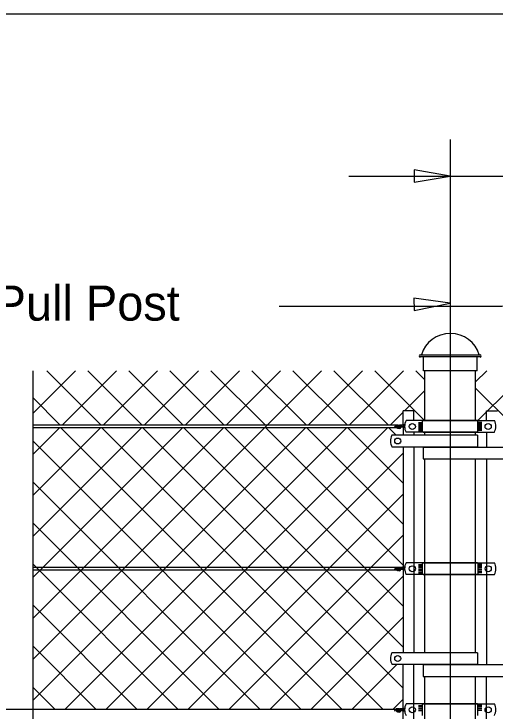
# Model space of a CAD drawing. Extents: x 0 to 41.1, y 0 to 26.4.
# Drawn here: x 23.735 to 26.501, y 22.394 to 26.4 of the extents above; entities that cross this region are included whole.
import ezdxf

# ---------------------------------------------------------------- set-up
doc = ezdxf.new("R2010")
doc.units = 0
for name, color, linetype in [('CL_Major', 7, 'Continuous'), ('Dimension', 7, 'Continuous'), ('Miscellaneous', 7, 'Continuous'), ('Miscellaneous1', 7, 'Continuous'), ('SteelMisc', 7, 'Continuous'), ('TextStructures', 7, 'Continuous')]:
    doc.layers.add(name, color=color, linetype=linetype)

msp = doc.modelspace()

# ---------------------------------------------------------------- linework, layer by layer
at = {"layer": 'CL_Major'}
msp.add_line((26.2429, 25.6784), (26.2429, 12.3953), dxfattribs=at)
at = {"layer": 'Dimension'}
msp.add_line((25.6609, 25.4682), (35.6727, 25.4682), dxfattribs=at)
for points in [[(26.2429, 25.4682), (26.0347, 25.5034), (26.0347, 25.4329)], [(26.2429, 24.737), (26.0337, 24.766), (26.0358, 24.6954)]]:
    msp.add_lwpolyline(points, close=True, dxfattribs=at)
msp.add_lwpolyline([(23.8431, 24.349), (23.8431, 21.1819), (23.9465, 21.1819), (23.8431, 21.1369), (23.7398, 21.0919), (23.8431, 21.0919), (23.8431, 20.1983)], dxfattribs=at)
msp.add_open_spline([(25.2588, 24.7214), (25.7125, 24.7214), (27.3088, 24.7214), (28.5763, 24.9737)], degree=2, dxfattribs=at)
at = {"layer": 'Miscellaneous'}
for p, q in [((24.0882, 24.349), (23.8431, 24.104)), ((24.2372, 24.0365), (23.9247, 24.349)), ((24.3239, 24.349), (24.0113, 24.0365)), ((24.4729, 24.0365), (24.1604, 24.349)), ((24.5596, 24.349), (24.247, 24.0365)), ((24.7086, 24.0365), (24.3961, 24.349)), ((24.7953, 24.349), (24.4827, 24.0365)), ((24.9443, 24.0365), (24.6318, 24.349)), ((25.031, 24.349), (24.7184, 24.0365)), ((25.18, 24.0365), (24.8675, 24.349)), ((25.2667, 24.349), (24.9541, 24.0365)), ((25.4157, 24.0365), (25.1032, 24.349)), ((25.5024, 24.349), (25.1898, 24.0365)), ((25.6514, 24.0365), (25.3389, 24.349)), ((25.7381, 24.349), (25.4255, 24.0365)), ((25.8871, 24.0365), (25.5746, 24.349)), ((25.9738, 24.349), (25.6612, 24.0365)), ((26.0957, 24.0637), (25.8103, 24.349)), ((26.0971, 24.298), (26.046, 24.349)), ((26.3887, 24.2852), (26.4526, 24.349)), ((26.4023, 24.0631), (26.6883, 24.349)), ((25.4108, 24.2575), (23.8431, 22.6898)), ((26.0971, 24.2366), (25.9803, 24.1198)), ((26.3887, 24.2494), (26.6017, 24.0365)), ((24.0015, 24.0365), (23.8431, 24.1949)), ((25.972, 24.1116), (25.8969, 24.0365)), ((25.4108, 24.0218), (23.8431, 22.4541)), ((24.9394, 24.0218), (23.8431, 22.9255)), ((24.7037, 24.0218), (23.8431, 23.1612)), ((24.468, 24.0218), (23.8431, 23.3969)), ((24.2323, 24.0218), (23.8431, 23.6326)), ((23.9966, 24.0218), (23.8431, 23.8683)), ((25.6205, 22.4048), (24.0035, 24.0218)), ((25.6465, 24.0218), (24.0295, 22.4048)), ((25.8562, 22.4048), (24.2392, 24.0218)), ((25.8822, 24.0218), (24.2652, 22.4048)), ((25.972, 22.5246), (24.4749, 24.0218)), ((25.972, 22.7603), (24.7106, 24.0218)), ((25.972, 22.996), (24.9463, 24.0218)), ((25.972, 23.2317), (25.182, 24.0218)), ((25.972, 23.4674), (25.4177, 24.0218)), ((25.972, 23.7031), (25.6534, 24.0218)), ((25.9323, 23.9786), (25.8891, 24.0218)), ((25.3848, 22.4048), (23.8431, 23.9464)), ((25.972, 23.8759), (24.5009, 22.4048)), ((25.1491, 22.4048), (23.8431, 23.7107)), ((25.972, 23.6402), (24.7366, 22.4048)), ((24.9134, 22.4048), (23.8431, 23.475)), ((25.972, 23.4045), (24.9723, 22.4048)), ((24.6777, 22.4048), (23.8431, 23.2393)), ((25.972, 23.1688), (25.208, 22.4048)), ((24.442, 22.4048), (23.8431, 23.0036)), ((25.972, 22.9331), (25.4437, 22.4048)), ((24.2063, 22.4048), (23.8447, 22.7664)), ((25.9356, 22.6609), (25.6794, 22.4048)), ((23.9706, 22.4048), (23.8431, 22.5322)), ((25.972, 22.4617), (25.9151, 22.4048))]:
    msp.add_line(p, q, dxfattribs=at)
at = {"layer": 'Miscellaneous1'}
msp.add_lwpolyline([(0, 26.4), (41.0667, 26.4), (41.0667, 0), (0, 0)], close=True, dxfattribs=at)
at = {"layer": 'SteelMisc'}
for p, q in [((26.0706, 24.441), (26.4152, 24.441)), ((26.4152, 24.4288), (26.0706, 24.4288)), ((26.0889, 24.349), (26.0889, 24.4288)), ((26.397, 24.349), (26.397, 24.4288)), ((26.397, 24.349), (26.0889, 24.349)), ((26.0971, 24.0636), (26.0971, 24.349)), ((26.3887, 24.0636), (26.3887, 24.349)), ((25.972, 24.0396), (25.972, 24.1198)), ((26.0345, 24.1198), (25.972, 24.1198)), ((26.0345, 24.0636), (26.0345, 24.1198)), ((26.4512, 24.0636), (26.4512, 24.1198)), ((26.4512, 24.1198), (26.5137, 24.1198)), ((25.9336, 24.0365), (23.8431, 24.0365)), ((25.9817, 24.0412), (25.9524, 24.0366)), ((25.972, 24.0366), (25.972, 23.9786)), ((26.3988, 24.0637), (25.989, 24.0637)), ((26.0604, 24.0528), (26.0833, 24.0528)), ((26.0604, 24.0473), (26.0833, 24.0473)), ((26.0604, 24.0393), (26.0833, 24.0393)), ((26.0833, 23.9959), (26.0833, 24.0637)), ((26.0872, 24.0637), (26.4969, 24.0637)), ((26.4254, 24.0528), (26.4024, 24.0528)), ((26.4254, 24.0473), (26.4024, 24.0473)), ((26.4254, 24.0393), (26.4024, 24.0393)), ((26.4025, 23.9959), (26.4025, 24.0637)), ((25.9349, 24.0218), (23.8431, 24.0218)), ((25.981, 24.0207), (25.9474, 24.0264)), ((25.9806, 24.0255), (25.9508, 24.0304)), ((25.9809, 24.0362), (25.9549, 24.0321)), ((25.972, 24.0347), (25.972, 24.0269)), ((26.0604, 24.0337), (26.0833, 24.0337)), ((26.0604, 24.0257), (26.0833, 24.0257)), ((26.0604, 24.0202), (26.0833, 24.0202)), ((26.0604, 24.0122), (26.0833, 24.0122)), ((26.0604, 24.0066), (26.0833, 24.0066)), ((26.4254, 24.0337), (26.4024, 24.0337)), ((26.4254, 24.0257), (26.4024, 24.0257)), ((26.4254, 24.0202), (26.4024, 24.0202)), ((26.4254, 24.0122), (26.4024, 24.0122)), ((26.4254, 24.0066), (26.4024, 24.0066)), ((26.3988, 23.9786), (25.9077, 23.9786)), ((26.3988, 23.9959), (25.9894, 23.9959)), ((26.0345, 23.9959), (26.0345, 23.9786)), ((26.0872, 23.9959), (26.4966, 23.9959)), ((26.0971, 23.9786), (26.0971, 23.9959)), ((26.3888, 23.9786), (26.3888, 23.9959)), ((26.3988, 23.9786), (26.3988, 23.9109)), ((26.4513, 23.9959), (26.4513, 23.9109)), ((26.3988, 23.9109), (25.9084, 23.9109)), ((25.972, 23.9109), (25.972, 22.7286)), ((26.0345, 23.9109), (26.0345, 22.7286)), ((26.0872, 23.9109), (26.0872, 23.8433)), ((26.0872, 23.9109), (26.5783, 23.9109)), ((26.0872, 23.8433), (26.5776, 23.8433)), ((26.0971, 22.7286), (26.0971, 23.8433)), ((26.3888, 22.7286), (26.3888, 23.8433)), ((26.4513, 23.8433), (26.4513, 22.6609)), ((26.3989, 23.2462), (25.9891, 23.2462)), ((26.0605, 23.2354), (26.0835, 23.2354)), ((26.0835, 23.1785), (26.0835, 23.2462)), ((26.0874, 23.2462), (26.4971, 23.2462)), ((26.4255, 23.2354), (26.4026, 23.2354)), ((26.4027, 23.1785), (26.4027, 23.2462)), ((25.9338, 23.219), (23.8433, 23.219)), ((25.9351, 23.2043), (23.8433, 23.2043)), ((25.9812, 23.2033), (25.9476, 23.2089)), ((25.9808, 23.2081), (25.951, 23.213)), ((25.9818, 23.2237), (25.9526, 23.2191)), ((25.9811, 23.2187), (25.9551, 23.2146)), ((25.9722, 23.2172), (25.9722, 23.2094)), ((26.0605, 23.2298), (26.0835, 23.2298)), ((26.0605, 23.2218), (26.0835, 23.2218)), ((26.0605, 23.2163), (26.0835, 23.2163)), ((26.0605, 23.2083), (26.0835, 23.2083)), ((26.0605, 23.2027), (26.0835, 23.2027)), ((26.4255, 23.2298), (26.4026, 23.2298)), ((26.4255, 23.2218), (26.4026, 23.2218)), ((26.4255, 23.2163), (26.4026, 23.2163)), ((26.4255, 23.2083), (26.4026, 23.2083)), ((26.4255, 23.2027), (26.4026, 23.2027)), ((26.3989, 23.1785), (25.9896, 23.1785)), ((26.0605, 23.1947), (26.0835, 23.1947)), ((26.0605, 23.1892), (26.0835, 23.1892)), ((26.0874, 23.1785), (26.4967, 23.1785)), ((26.4255, 23.1947), (26.4026, 23.1947)), ((26.4255, 23.1892), (26.4026, 23.1892)), ((26.4513, 22.9288), (26.4513, 22.7653)), ((26.3988, 22.7286), (25.9077, 22.7286)), ((26.3988, 22.7286), (26.3988, 22.6609)), ((26.3988, 22.6609), (25.9084, 22.6609)), ((25.972, 21.4785), (25.972, 22.6609)), ((26.0345, 21.4785), (26.0345, 22.6609)), ((26.0872, 22.6609), (26.0872, 22.5933)), ((26.0872, 22.6609), (26.5783, 22.6609)), ((26.0872, 22.5933), (26.5776, 22.5933)), ((26.0971, 21.4785), (26.0971, 22.5933)), ((26.3888, 21.4785), (26.3888, 22.5933)), ((26.4513, 21.4109), (26.4513, 22.5933)), ((26.3988, 22.4358), (25.989, 22.4358)), ((26.0833, 22.3681), (26.0833, 22.4358)), ((26.0872, 22.4358), (26.4969, 22.4358)), ((26.4025, 22.3681), (26.4025, 22.4358)), ((22.5265, 22.4048), (25.929, 22.4048)), ((25.9815, 22.3908), (25.9472, 22.3965)), ((25.9809, 22.3956), (25.9504, 22.4006)), ((25.9811, 22.4112), (25.9549, 22.4069)), ((25.9807, 22.4063), (25.955, 22.402)), ((25.972, 22.4048), (25.972, 22.397)), ((26.0604, 22.425), (26.0833, 22.425)), ((26.0604, 22.4195), (26.0833, 22.4195)), ((26.0604, 22.4114), (26.0833, 22.4114)), ((26.0604, 22.4059), (26.0833, 22.4059)), ((26.0604, 22.3979), (26.0833, 22.3979)), ((26.4254, 22.425), (26.4024, 22.425)), ((26.4254, 22.4195), (26.4024, 22.4195)), ((26.4254, 22.4114), (26.4024, 22.4114)), ((26.4254, 22.4059), (26.4024, 22.4059)), ((26.4254, 22.3979), (26.4024, 22.3979))]:
    msp.add_line(p, q, dxfattribs=at)
for centre, start, end in [((26.0707, 24.4347), 91.1647, 268.8353), ((26.415, 24.4347), 271.1647, 88.8353)]:
    msp.add_arc(centre, 0.00613, start, end, dxfattribs=at)
for centre, major_axis, ratio, start_param, end_param in [((26.2436, 24.4), (0.1711, 0), 0.957868, 0.252602, 2.888574), ((25.9368, 24.0233), (0.0142, 0), 0.957868, 1.486836, 3.141593), ((25.9415, 24.0288), (0.00872, 0), 0.957868, 1.29026, 2.959852), ((25.948, 24.0283), (0.00872, 0), 0.957868, 1.29026, 4.182385), ((25.9537, 24.0274), (-0.0115, -0.0041), 0.737732, 4.35367, 7.47816), ((26.0582, 24.03), (-0.0776, 0), 0.957868, 5.81433, 6.762456), ((26.4276, 24.03), (0.0776, 0), 0.957868, 5.803915, 6.752041), ((25.9448, 24.0082), (-0.0274, 0), 0.957868, 5.133531, 5.654664), ((25.9419, 24.0278), (-0.00944, 0), 0.957868, 6.009018, 8.249874), ((25.9415, 24.0288), (0.00503, 0), 0.92697, 1.570796, 4.502291), ((25.9525, 24.0259), (-0.00527, 0), 0.957868, 5.22362, 7.507542), ((25.9503, 24.025), (-0.00301, 0), 0.957868, 6.141288, 6.278592), ((25.9556, 24.0225), (-0.00982, 0), 0.957868, 4.777514, 5.62749), ((25.9503, 24.025), (-0.00301, 0), 0.957868, 1.11255, 2.999696), ((25.9497, 24.0272), (0.00453, 0), 0.957868, 0.731188, 1.133458), ((25.9498, 24.0267), (0.0095, 0), 0.957868, 5.011765, 6.030719), ((25.9498, 24.0267), (0.0095, 0), 0.957868, 0.230606, 0.609214), ((25.9771, 23.9454), (-0.0776, 0), 0.957868, 5.821213, 6.765127), ((26.0584, 23.2125), (-0.0776, 0), 0.957868, 5.81433, 6.762456), ((26.4277, 23.2125), (0.0776, 0), 0.957868, 5.803915, 6.752041), ((25.9449, 23.1908), (-0.0274, 0), 0.957868, 5.133531, 5.654664), ((25.9369, 23.2058), (0.0142, 0), 0.957868, 1.486836, 3.141593), ((25.9421, 23.2104), (-0.00944, 0), 0.957868, 6.009018, 8.249874), ((25.9417, 23.2113), (0.00872, 0), 0.957868, 1.29026, 2.959852), ((25.9417, 23.2113), (0.00503, 0), 0.92697, 1.570796, 4.502291), ((25.9482, 23.2108), (0.00872, 0), 0.957868, 1.29026, 4.182385), ((25.9539, 23.2099), (-0.0115, -0.0041), 0.737732, 4.35367, 7.47816), ((25.9526, 23.2084), (-0.00527, 0), 0.957868, 5.22362, 7.507542), ((25.9505, 23.2075), (-0.00301, 0), 0.957868, 6.141288, 6.278592), ((25.9558, 23.205), (-0.00982, 0), 0.957868, 4.777514, 5.62749), ((25.9505, 23.2075), (-0.00301, 0), 0.957868, 1.11255, 2.999696), ((25.9498, 23.2097), (0.00453, 0), 0.957868, 0.731188, 1.133458), ((25.9499, 23.2092), (0.0095, 0), 0.957868, 5.011765, 6.030719), ((25.9499, 23.2092), (0.0095, 0), 0.957868, 0.230606, 0.609214), ((25.9771, 22.6954), (-0.0776, 0), 0.957868, 5.821213, 6.765127), ((26.0582, 22.4022), (-0.0776, 0), 0.957868, 5.81433, 6.762456), ((26.4276, 22.4022), (0.0776, 0), 0.957868, 5.803915, 6.752041), ((25.9368, 22.3934), (0.0142, 0), 0.957868, 1.427866, 3.10804), ((25.9448, 22.3784), (-0.0274, 0), 0.957868, 5.133531, 5.652105), ((25.9419, 22.398), (-0.00944, 0), 0.957868, 5.913863, 8.249874), ((25.9415, 22.3989), (0.00872, 0), 0.957868, 1.103089, 2.861068), ((25.9415, 22.3989), (0.00503, 0), 0.92697, 1.632124, 4.493683), ((25.948, 22.3984), (0.00872, 0), 0.957868, 1.202886, 4.168248), ((25.9537, 22.3976), (-0.0115, -0.0041), 0.737732, 4.35367, 7.518104), ((25.9525, 22.396), (-0.00527, 0), 0.957868, 5.822913, 6.90541), ((25.9503, 22.3951), (-0.00301, 0), 0.957868, 5.79353, 6.278592), ((25.9556, 22.3927), (-0.00982, 0), 0.957868, 4.777514, 5.64637), ((25.9503, 22.3951), (-0.00301, 0), 0.957868, 0.785393, 3.285656), ((25.9497, 22.3973), (0.00453, 0), 0.957868, 0.731188, 1.133458), ((25.9498, 22.3968), (0.0095, 0), 0.957868, 5.036011, 6.030719), ((25.9498, 22.3968), (0.0095, 0), 0.957868, 0.267283, 0.660004)]:
    msp.add_ellipse(centre, major_axis=major_axis, ratio=ratio, start_param=start_param, end_param=end_param, dxfattribs=at)
for centre, major_axis in [((26.0249, 24.0291), (0.0178, 0)), ((26.4609, 24.0291), (-0.0178, 0)), ((25.9412, 23.9458), (0.0177, 0)), ((26.025, 23.2117), (0.0178, 0)), ((26.4611, 23.2117), (-0.0178, 0)), ((25.9412, 22.6958), (0.0177, 0)), ((26.0249, 22.4013), (0.0178, 0)), ((26.4609, 22.4013), (-0.0178, 0))]:
    msp.add_ellipse(centre, major_axis=major_axis, ratio=0.957868, dxfattribs=at)

# ---------------------------------------------------------------- texts
at = {"layer": 'TextStructures'}
msp.add_text('℄ Pull Post', height=0.2016, dxfattribs=at).set_placement((23.4401, 24.6377))

doc.saveas('drawing.dxf')
